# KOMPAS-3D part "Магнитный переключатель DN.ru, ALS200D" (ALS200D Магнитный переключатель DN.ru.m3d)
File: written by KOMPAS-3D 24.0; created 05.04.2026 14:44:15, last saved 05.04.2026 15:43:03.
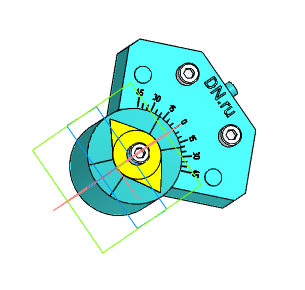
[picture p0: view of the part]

Document properties: Автор: R2D2; Полное имя файла: E:\Работа\Зайцев\Аксессуары для пневмоприводов\Электропневматические позиционеры DN.ru\ALS200D Магнитный переключатель DN.ru\ALS200D Магнитный переключатель DN.ru.m3d

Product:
- Part/product: Магнитный переключатель DN.ru  | designation ALS200D
    Масса: 0.14
    Раздел спецификации: Прочие изделия
    Примечание: D290-00318

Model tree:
1. Операция без истории:2

Referenced files in C:\Program Files\ASCON\KOMPAS-3D v24\Libs\PolynomLib\DATA\vault\Methods\Kompas\3D\: PLib_Screw_DIN_7984_1500.m3d
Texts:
  ALS200D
